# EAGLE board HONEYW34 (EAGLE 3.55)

No outline drawn. Coordinates in mm, seen from the top.
Copper layers used: 

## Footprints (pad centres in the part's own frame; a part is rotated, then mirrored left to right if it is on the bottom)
A-3 = drill 0.61 pad 1.397 octagon:  -2.54,-1.27;  -3.81,0;  -2.54,1.27
A-4 = drill 0.61 pad 1.397 octagon:  -2.54,-1.27;  -4.064,0;  -2.54,1.27;  -1.27,0

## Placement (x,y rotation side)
AAA-3  [A-3]  39.37,26.67 0 top
AAA-4  [A-4]  39.37,41.91 0 top
ABA-3  [A-3]  41.91,59.69 0 top
ABA-4  [A-4]  44.45,80.01 0 top
ADA-3  [A-3]  41.91,97.79 0 top
ADA-4  [A-4]  41.91,118.11 0 top
BAA-3  [A-3]  39.37,138.43 0 top
BAA-4  [A-4]  41.91,153.67 0 top
BBA-1  [-35SC]  0,0 0 top
BBA-3  [A-3]  41.91,171.45 0 top
BBA-4  [A-4]  41.91,189.23 0 top

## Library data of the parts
AAA-3 AAA-4 ABA-3 ABA-4 ADA-3 ADA-4 BAA-3 BAA-4 BBA-3 BBA-4 = HONY3000
BBA-1 = frames

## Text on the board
tPlace: 10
